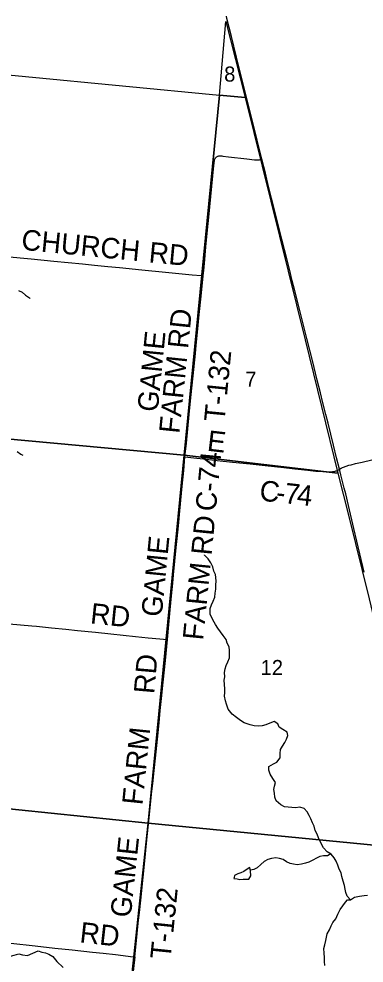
# Model space of a CAD drawing. Extents: x 831 to 1552, y 430 to 870.
# Drawn here: x 1029.7 to 1048.8, y 725.1 to 777.4 of the extents above; entities that cross this region are included whole.
import ezdxf

# ---------------------------------------------------------------- set-up
doc = ezdxf.new("R2010")
doc.units = 0
for name, color, linetype in [('GM_X_Corporation', 7, 'Continuous'), ('GM_X_County_Road', 7, 'Continuous'), ('GM_X_County_Road_Text', 7, 'Continuous'), ('GM_X_Minor_Lake', 7, 'Continuous'), ('GM_X_Minor_River', 7, 'Continuous'), ('GM_X_Section_Text', 7, 'Continuous'), ('GM_X_Township_Road', 7, 'Continuous'), ('GM_X_Township_Road_Text', 7, 'Continuous')]:
    doc.layers.add(name, color=color, linetype=linetype)

msp = doc.modelspace()

# ---------------------------------------------------------------- linework, layer by layer
at = {"layer": 'GM_X_Corporation'}
for points in [[(1040.822, 773.14), (1041.178, 777.218), (1042.252, 773.008)], [(1019.314, 775.201), (1040.822, 773.14), (1038.88, 753.198), (1017.196, 755.179)], [(1040.822, 773.14), (1042.252, 773.008), (1045.577, 759.575), (1047.388, 752.193), (1038.88, 753.198)], [(1017.196, 755.179), (1038.88, 753.198), (1036.878, 732.803), (1015.357, 735.031)], [(1038.88, 753.198), (1047.388, 752.193), (1047.984, 749.863), (1049.126, 745.226), (1052.432, 731.297), (1036.878, 732.803)], [(1015.357, 735.031), (1036.878, 732.803), (1034.738, 712.834), (1013.944, 715)], [(1036.878, 732.803), (1052.432, 731.297), (1052.759, 730.026), (1055.607, 718.06), (1054.834, 710.548), (1034.738, 712.834)]]:
    msp.add_lwpolyline(points, close=True, dxfattribs=at)
at = {"layer": 'GM_X_County_Road'}
for points in [[(1043.174, 769.584), (1042.908, 770.639), (1042.575, 771.99), (1042.328, 773.004), (1041.772, 775.247), (1041.491, 776.394), (1041.241, 777.382), (1041.21, 777.515)], [(1047.477, 752.408), (1047.314, 753.054), (1047.143, 753.741), (1046.844, 754.96), (1046.726, 755.443), (1046.561, 756.093), (1046.419, 756.647), (1046.243, 757.346), (1045.973, 758.431), (1045.662, 759.66), (1045.518, 760.239), (1045.28, 761.204), (1045.006, 762.288), (1044.862, 762.854), (1044.701, 763.493), (1044.561, 764.06), (1044.292, 765.132), (1044.106, 765.893), (1043.954, 766.495), (1043.719, 767.435), (1043.553, 768.073), (1043.37, 768.808), (1043.174, 769.584)], [(1047.477, 752.408), (1047.572, 752.467), (1047.646, 752.508), (1047.693, 752.53), (1047.751, 752.555), (1047.798, 752.571), (1047.85, 752.588), (1047.994, 752.63), (1048.124, 752.663), (1048.364, 752.724), (1048.725, 752.812), (1049.801, 753.068), (1050.924, 753.339), (1051.674, 753.516), (1052.64, 753.75), (1053.568, 753.983), (1054.111, 754.117), (1054.751, 754.272), (1056.045, 754.576), (1057.156, 754.843), (1058.002, 755.046), (1058.665, 755.207)], [(1037.945, 742.988), (1038.045, 744.017), (1038.103, 744.623), (1038.176, 745.402), (1038.241, 746.095), (1038.287, 746.564), (1038.434, 748.085), (1038.48, 748.568), (1038.555, 749.284), (1038.635, 750.113), (1038.762, 751.473), (1038.844, 752.339), (1038.916, 753.097)], [(1038.916, 753.097), (1039.567, 753.027), (1039.938, 752.986), (1040.704, 752.904), (1041.542, 752.814), (1042.532, 752.707), (1043.36, 752.62), (1044.386, 752.509), (1045.006, 752.436), (1045.718, 752.357), (1046.175, 752.31), (1046.547, 752.28), (1046.746, 752.273), (1046.909, 752.272), (1047.004, 752.275), (1047.084, 752.28), (1047.131, 752.285), (1047.184, 752.295), (1047.237, 752.306), (1047.282, 752.318), (1047.326, 752.333), (1047.377, 752.354), (1047.415, 752.372), (1047.456, 752.394), (1047.477, 752.408)], [(1048.853, 746.716), (1048.438, 748.431), (1048.272, 749.132), (1047.971, 750.402), (1047.82, 751.042), (1047.74, 751.368), (1047.633, 751.802), (1047.556, 752.103), (1047.477, 752.408)], [(1029.176, 743.858), (1030.422, 743.742), (1030.694, 743.717), (1031.521, 743.634), (1032.31, 743.555), (1032.965, 743.487), (1033.957, 743.384), (1034.802, 743.299), (1036.167, 743.151), (1036.877, 743.078), (1037.945, 742.988)]]:
    msp.add_lwpolyline(points, dxfattribs=at)
at = {"layer": 'GM_X_Minor_Lake'}
for points in [[(1042.553, 730.17), (1042.517, 730.344), (1042.357, 730.263), (1042.18, 730.129), (1042.012, 730.064), (1041.837, 730.005), (1041.668, 729.909), (1041.639, 729.791)], [(1041.639, 729.791), (1041.628, 729.743), (1041.81, 729.718), (1041.961, 729.686), (1042.136, 729.699), (1042.295, 729.697), (1042.447, 729.71), (1042.556, 729.883), (1042.553, 730.17)]]:
    msp.add_lwpolyline(points, dxfattribs=at)
at = {"layer": 'GM_X_Minor_River'}
for points in [[(1029.698, 762.311), (1029.887, 762.225), (1030.084, 762.048), (1030.296, 761.901), (1030.334, 761.878)], [(1029.61, 753.39), (1029.83, 753.251), (1029.936, 753.197)], [(1040.344, 747.223), (1040.209, 747.445), (1040.005, 747.652), (1039.99, 747.675)], [(1048.083, 728.553), (1047.91, 728.767), (1047.828, 728.958), (1047.791, 729.148), (1047.748, 729.353), (1047.674, 729.597), (1047.6, 729.855), (1047.564, 730.053), (1047.459, 730.267), (1047.385, 730.472), (1047.288, 730.693), (1047.191, 730.892), (1047.018, 731.09), (1046.798, 731.214), (1046.595, 731.443), (1046.467, 731.68), (1046.318, 731.993), (1046.244, 732.198), (1046.139, 732.404), (1046.08, 732.64), (1045.991, 732.831), (1045.886, 733.044), (1045.804, 733.235), (1045.692, 733.433), (1045.518, 733.625), (1045.283, 733.687), (1045.047, 733.659), (1044.833, 733.668), (1044.423, 733.718), (1044.233, 733.818), (1043.977, 734.048), (1043.902, 734.246), (1043.874, 734.467), (1043.845, 734.664), (1043.878, 734.861), (1043.925, 735.059), (1043.782, 735.288), (1043.632, 735.524), (1043.566, 735.745), (1043.568, 735.943), (1043.82, 736.093), (1044.012, 736.19), (1044.189, 736.424), (1044.183, 736.667), (1044.208, 736.879), (1044.324, 737.068), (1044.448, 737.273), (1044.541, 737.469), (1044.611, 737.659), (1044.583, 737.856), (1044.34, 737.988), (1044.144, 738.119), (1044.062, 738.317), (1043.85, 738.44), (1043.613, 738.351), (1043.399, 738.262), (1043.193, 738.195), (1042.994, 738.174), (1042.743, 738.191), (1042.531, 738.261), (1042.204, 738.371), (1041.985, 738.494), (1041.765, 738.656), (1041.523, 738.848), (1041.305, 739.115), (1041.224, 739.39), (1041.165, 739.58), (1041.114, 739.839), (1041.123, 740.052), (1041.125, 740.25), (1041.105, 740.493), (1041.091, 740.729), (1041.131, 740.918), (1041.111, 741.154), (1041.15, 741.352), (1041.19, 741.541), (1041.291, 741.753), (1041.392, 741.958), (1041.379, 742.178), (1041.388, 742.376), (1041.367, 742.582), (1041.255, 742.773), (1041.196, 742.978), (1041.038, 743.2), (1040.88, 743.399), (1040.729, 743.606), (1040.602, 743.82), (1040.452, 744.065), (1040.318, 744.385), (1040.305, 744.69), (1040.391, 744.91), (1040.469, 745.099), (1040.563, 745.334), (1040.587, 745.555), (1040.62, 745.775), (1040.629, 745.995), (1040.647, 746.231), (1040.604, 746.574), (1040.515, 746.765), (1040.456, 747.001), (1040.344, 747.223)], [(1046.996, 731.102), (1046.804, 731.001), (1046.583, 730.988), (1046.392, 730.967), (1046.201, 730.87), (1046.002, 730.765), (1045.78, 730.653), (1045.589, 730.594), (1045.375, 730.528), (1045.139, 730.5), (1044.926, 730.539), (1044.736, 730.564), (1044.547, 730.664), (1044.35, 730.795), (1044.153, 730.85), (1043.955, 730.882), (1043.711, 730.854), (1043.505, 730.787), (1043.306, 730.683), (1043.114, 730.51), (1042.914, 730.329), (1042.723, 730.247), (1042.548, 730.196)], [(1046.786, 726.667), (1046.918, 726.901), (1047.011, 727.113), (1047.112, 727.309), (1047.266, 727.513), (1047.383, 727.77), (1047.507, 728.027), (1047.669, 728.223), (1047.815, 728.434), (1047.926, 728.559), (1048.083, 728.553), (1048.313, 728.703), (1048.587, 728.769), (1048.839, 728.797), (1049.037, 728.818)], [(1046.663, 724.923), (1046.65, 725.151), (1046.645, 725.356), (1046.632, 725.614), (1046.611, 725.864), (1046.659, 726.076), (1046.722, 726.311), (1046.786, 726.667)], [(1028.245, 724.968), (1028.514, 725.2), (1028.774, 725.327), (1029.056, 725.407), (1029.247, 725.444), (1029.453, 725.495), (1029.705, 725.561), (1029.91, 725.513), (1030.199, 725.473), (1030.78, 725.726), (1030.977, 725.656), (1031.183, 725.631), (1031.38, 725.546), (1031.592, 725.415), (1031.825, 725.14), (1032.165, 724.811)]]:
    msp.add_lwpolyline(points, dxfattribs=at)
at = {"layer": 'GM_X_Township_Road'}
for points in [[(1039.922, 763.126), (1039.952, 763.429), (1040.01, 764.036), (1040.077, 764.741), (1040.159, 765.669), (1040.231, 766.386), (1040.402, 768.092), (1040.511, 769.243), (1040.525, 769.369), (1040.535, 769.443), (1040.543, 769.488), (1040.551, 769.526), (1040.56, 769.558), (1040.569, 769.582), (1040.576, 769.6), (1040.588, 769.624), (1040.606, 769.652), (1040.624, 769.676), (1040.65, 769.702), (1040.673, 769.721), (1040.698, 769.738), (1040.729, 769.752), (1040.761, 769.763), (1040.797, 769.771), (1040.837, 769.775), (1040.896, 769.776), (1040.93, 769.775), (1040.966, 769.771), (1041.016, 769.765), (1041.336, 769.721), (1042.348, 769.603), (1042.769, 769.557), (1042.85, 769.551), (1042.931, 769.546), (1042.969, 769.548), (1043.002, 769.549), (1043.041, 769.554), (1043.086, 769.563), (1043.174, 769.584)], [(1028.981, 764.206), (1030.385, 764.064), (1031.654, 763.946), (1033.236, 763.789), (1033.903, 763.72), (1034.64, 763.644), (1035.296, 763.58), (1036.52, 763.455), (1037.843, 763.324), (1039.315, 763.185), (1039.809, 763.137), (1039.922, 763.126)], [(1038.916, 753.097), (1038.992, 753.849), (1039.153, 755.443), (1039.247, 756.395), (1039.37, 757.582), (1039.407, 757.94), (1039.494, 758.831), (1039.54, 759.276), (1039.611, 760.005), (1039.707, 760.982), (1039.81, 762.008), (1039.922, 763.126)], [(1037.945, 742.988), (1038.045, 744.017), (1038.103, 744.623), (1038.176, 745.402), (1038.241, 746.095), (1038.287, 746.564), (1038.434, 748.085), (1038.48, 748.568), (1038.555, 749.284), (1038.635, 750.113), (1038.762, 751.473), (1038.844, 752.339), (1038.916, 753.097)], [(1036.136, 725.397), (1036.233, 726.31), (1036.329, 727.275), (1036.389, 727.856), (1036.466, 728.547), (1036.597, 729.808), (1036.711, 730.908), (1036.771, 731.513), (1036.842, 732.231), (1036.952, 733.293), (1037.066, 734.418), (1037.126, 735.012), (1037.203, 735.716), (1037.277, 736.407), (1037.386, 737.458), (1037.477, 738.36), (1037.545, 739.04), (1037.615, 739.72), (1037.703, 740.623), (1037.828, 741.822), (1037.945, 742.988)], [(1029.262, 726.158), (1030.621, 726.006), (1031.696, 725.89), (1032.659, 725.787), (1033.794, 725.664), (1034.375, 725.6), (1035.066, 725.523), (1036.04, 725.408), (1036.136, 725.397)], [(1036.136, 725.397), (1036.047, 724.593), (1035.95, 723.729), (1035.823, 722.543), (1035.799, 722.288)]]:
    msp.add_lwpolyline(points, dxfattribs=at)

# ---------------------------------------------------------------- texts
at = {"layer": 'GM_X_County_Road_Text'}
for s, height, rotation, p in [('E', 1.136, 353.2899, (1040.106, 753.444)), ('C-74', 1.1364, 84.6005, (1040.621, 750.044)), ('C', 1.136, 353.7677, (1043.005, 750.686)), ('7', 1.136, 353.7062, (1044.385, 750.535)), ('4', 1.136, 353.8594, (1045.079, 750.459)), ('-', 1.136, 353.7566, (1043.926, 750.585)), ('FARM RD', 1.1364, 84.3355, (1039.919, 742.911)), ('GAME', 1.1364, 84.4495, (1037.625, 744.205)), ('RD', 1.1364, 354.1024, (1033.637, 743.876))]:
    msp.add_text(s, height=height, rotation=rotation, dxfattribs=at).set_placement(p)
at = {"layer": 'GM_X_Section_Text'}
for s, height, p in [('8', 0.837, (1041.088, 773.885)), ('7', 0.837, (1042.254, 756.979)), ('12', 0.8371, (1043.104, 741.008))]:
    msp.add_text(s, height=height, rotation=0, dxfattribs=at).set_placement(p)
at = {"layer": 'GM_X_Township_Road_Text'}
for s, rotation, p in [('CHURCH', 354.4001, (1029.816, 764.579)), ('RD', 354.5839, (1036.88, 763.879)), ('FARM RD', 84.1858, (1038.605, 754.359)), ('GAME', 84.4053, (1037.407, 755.557)), ('T-132', 84.4026, (1041.101, 755.009)), ('RD', 85.0312, (1037.209, 739.939)), ('FARM', 84.1963, (1036.559, 733.778)), ('GAME', 84.0147, (1035.909, 727.546)), ('T-132', 84.1528, (1038.118, 725.237)), ('RD', 353.6064, (1033.047, 726.21))]:
    msp.add_text(s, height=1.1364, rotation=rotation, dxfattribs=at).set_placement(p)

doc.saveas('drawing.dxf')
